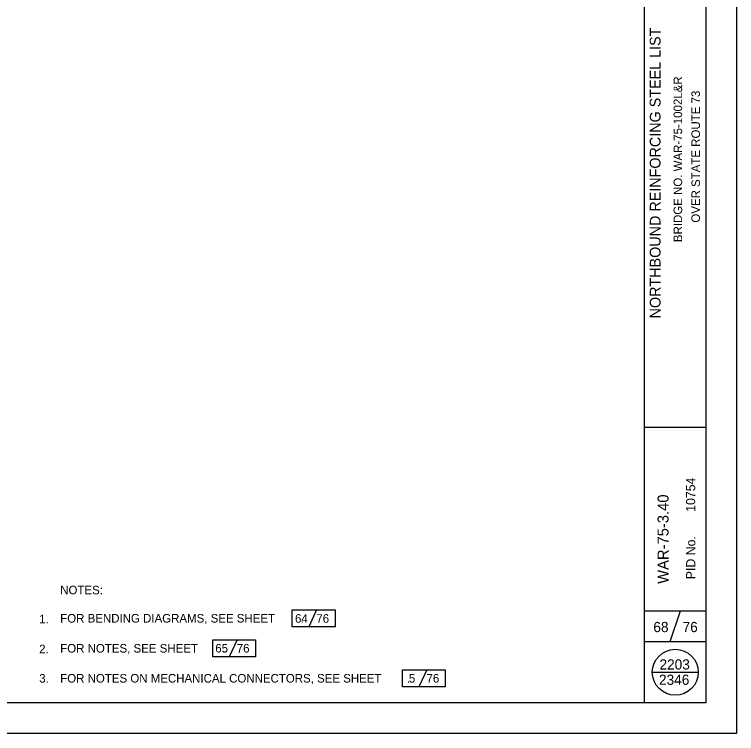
# Model space of a CAD drawing. Extents: x 1485751 to 1485785, y 230696.6 to 230718.6.
# Drawn here: x 1485773.25 to 1485785.03, y 230696.64 to 230708.38 of the extents above; entities that cross this region are included whole.
import ezdxf

# ---------------------------------------------------------------- set-up
doc = ezdxf.new("R2010")
doc.units = 0
for name, color, linetype in [('BR_P_Gen_Text', 7, 'Continuous'), ('BR_P_Sub_Text', 7, 'Continuous'), ('SH_Border', 7, 'Continuous'), ('SH_Cut_Line', 7, 'Continuous'), ('SH_Data', 7, 'Continuous'), ('TX_P_Misc', 7, 'Continuous')]:
    doc.layers.add(name, color=color, linetype=linetype)

msp = doc.modelspace()

# ---------------------------------------------------------------- linework, layer by layer
at = {"layer": 'BR_P_Gen_Text'}
for p, q in [((1485778.18, 230698.658), (1485778.052, 230698.38)), ((1485776.882, 230698.172), (1485776.753, 230697.894)), ((1485779.978, 230697.681), (1485779.85, 230697.403))]:
    msp.add_line(p, q, dxfattribs=at)
for points in [[(1485777.783, 230698.658), (1485778.48, 230698.658), (1485778.48, 230698.38), (1485777.783, 230698.38)], [(1485777.783, 230698.658), (1485778.48, 230698.658), (1485778.48, 230698.38), (1485777.783, 230698.38)], [(1485776.485, 230698.172), (1485777.181, 230698.172), (1485777.181, 230697.894), (1485776.485, 230697.894)], [(1485776.485, 230698.172), (1485777.181, 230698.172), (1485777.181, 230697.894), (1485776.485, 230697.894)], [(1485779.582, 230697.681), (1485780.278, 230697.681), (1485780.278, 230697.403), (1485779.582, 230697.403)], [(1485779.582, 230697.681), (1485780.278, 230697.681), (1485780.278, 230697.403), (1485779.582, 230697.403)]]:
    msp.add_lwpolyline(points, close=True, dxfattribs=at)
at = {"layer": 'SH_Border'}
for p, q in [((1485783.533, 230697.141), (1485783.533, 230718.141)), ((1485783.533, 230697.141), (1485783.533, 230718.141)), ((1485783.533, 230697.141), (1485783.533, 230718.141)), ((1485783.533, 230701.641), (1485784.533, 230701.641)), ((1485783.533, 230701.641), (1485784.533, 230701.641)), ((1485783.533, 230701.641), (1485784.533, 230701.641)), ((1485783.533, 230698.641), (1485784.533, 230698.641)), ((1485783.95, 230698.141), (1485784.116, 230698.641)), ((1485783.533, 230698.141), (1485784.533, 230698.141))]:
    msp.add_line(p, q, dxfattribs=at)
msp.add_lwpolyline([(1485753.033, 230718.141), (1485784.533, 230718.141), (1485784.533, 230697.141), (1485753.033, 230697.141)], close=True, dxfattribs=at)
at = {"layer": 'SH_Cut_Line'}
msp.add_lwpolyline([(1485751.033, 230718.641), (1485785.033, 230718.641), (1485785.033, 230696.641), (1485751.033, 230696.641)], close=True, dxfattribs=at)
at = {"layer": 'SH_Data'}
msp.add_line((1485783.658, 230697.641), (1485784.408, 230697.641), dxfattribs=at)
msp.add_line((1485783.658, 230697.641), (1485784.408, 230697.641), dxfattribs=at)
msp.add_line((1485783.658, 230697.641), (1485784.408, 230697.641), dxfattribs=at)
msp.add_circle((1485784.033, 230697.641), 0.375, dxfattribs=at)

# ---------------------------------------------------------------- texts
at = {"layer": 'BR_P_Gen_Text'}
for s, p in [('64', (1485777.827, 230698.449)), ('76', (1485778.175, 230698.449)), ('65', (1485776.526, 230697.963)), ('76', (1485776.876, 230697.963)), ('5', (1485779.685, 230697.472)), ('76', (1485779.973, 230697.472))]:
    msp.add_text(s, height=0.14, dxfattribs=at).set_placement(p)
at = {"layer": 'BR_P_Sub_Text'}
msp.add_text('WAR-75-3.40', height=0.18, rotation=90, dxfattribs=at).set_placement((1485783.923, 230699.084))
at = {"layer": 'SH_Data'}
for s, height, p in [('     NORTHBOUND REINFORCING STEEL LIST    ', 0.175, (1485783.792, 230703.09)), ('BRIDGE NO. WAR-75-1002L&R', 0.14, (1485784.145, 230704.66)), ('OVER STATE ROUTE 73', 0.14, (1485784.436, 230704.978)), ('10754', 0.15, (1485784.358, 230700.259)), ('PID No.', 0.15, (1485784.36, 230699.16))]:
    msp.add_text(s, height=height, rotation=90, dxfattribs=at).set_placement(p)
for s, p in [('68', (1485783.675, 230698.296)), ('76', (1485784.152, 230698.296)), ('2203', (1485783.775, 230697.686)), ('2346', (1485783.767, 230697.436))]:
    msp.add_text(s, height=0.1666, dxfattribs=at).set_placement(p)
at = {"layer": 'TX_P_Misc'}
for s, p in [('NOTES:', (1485773.995, 230698.913)), ('1.', (1485773.652, 230698.44)), ('FOR BENDING DIAGRAMS, SEE SHEET        .', (1485773.995, 230698.452)), ('2.', (1485773.652, 230697.952)), ('FOR NOTES, SEE SHEET        .', (1485773.995, 230697.962)), ('3.', (1485773.652, 230697.472)), ('FOR NOTES ON MECHANICAL CONNECTORS, SEE SHEET        .', (1485773.995, 230697.473))]:
    msp.add_text(s, height=0.14, dxfattribs=at).set_placement(p)

doc.saveas('drawing.dxf')
